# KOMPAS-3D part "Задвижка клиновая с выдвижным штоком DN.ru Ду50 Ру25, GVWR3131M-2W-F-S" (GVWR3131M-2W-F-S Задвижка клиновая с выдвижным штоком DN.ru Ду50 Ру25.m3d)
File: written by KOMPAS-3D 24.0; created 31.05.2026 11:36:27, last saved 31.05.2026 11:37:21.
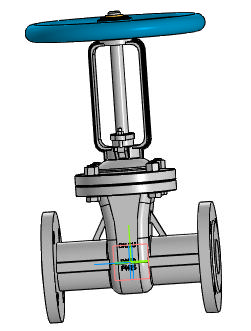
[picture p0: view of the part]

Document properties: Автор: R2D2; Полное имя файла: E:\Работа\Зайцев\GVWR3131M-2W-F-S Задвижка клиновая 30нж64нж DN.ru  Ду50-150 Ру25\исходные данные\DN50\GVWR3131M-2W-F-S Задвижка клиновая с выдвижным штоком DN.ru Ду50 Ру25.m3d

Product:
- Component [detail]: Деталь2  | qty 1  | pos. 1  | Масса: 3.95529; Автор: R2D2; additional columns: Типовые; source file: Деталь2 Деталь2.m3d
- Component [detail]: AS 1110 - M12 x 45  | qty 4  | pos. 2  | Комментарий: Болты и винты   шестигранные точные   метрические ISO; Автор: R2D2; additional columns: Сталь, мягкая; source file: AS 1110 - M12 x 45 AS 1110 - M12 x 45.m3d
- Component [detail]: ANSI B18.2.4.2M - M12x1,75 - 18  | designation ANSI B18.2.4.2M - M12x1,75  | qty 4  | pos. 3  | Комментарий: Типы метрических   шестигранных гаек   2; Автор: R2D2; additional columns: Сталь, мягкая; source file: ANSI B18.2.4.2M - M12x1,75 ANSI B18.2.4.2M - M12x1,75 - 18.m3d
- Component [detail]: ANSI B18.2.4.2M - M5x0,8 - 8  | designation ANSI B18.2.4.2M - M5x0,8  | qty 1  | pos. 4  | Комментарий: Типы метрических   шестигранных гаек   2; Автор: R2D2; additional columns: Сталь, мягкая; source file: ANSI B18.2.4.2M - M5x0,8 ANSI B18.2.4.2M - M5x0,8 - 8.m3d
- Component [detail]: Деталь1  | qty 1  | pos. 5  | Автор: R2D2; additional columns: Типовые; source file: 2.m3d
- Component [detail]: Деталь1  | qty 1  | pos. 5  | Автор: R2D2; additional columns: Типовые; source file: 1.m3d
- Component [detail]: Деталь1  | designation Деталь1-01  | qty 1  | pos. 6  | Автор: R2D2; additional columns: Типовые; source file: 1.m3d
- Component [detail]: ANSI B18.2.4.2M - M5x0,8 - 8  | designation ANSI B18.2.4.2M - M5x0,8-01  | qty 1  | pos. 7  | Комментарий: Типы метрических   шестигранных гаек   2; Автор: R2D2; additional columns: Сталь, мягкая; source file: ANSI B18.2.4.2M - M5x0,8 ANSI B18.2.4.2M - M5x0,8 - 8.m3d
- Component [detail]: Деталь1  | qty 1  | Автор: R2D2; additional columns: Типовые; source file: 3.m3d
- Part/product: Задвижка клиновая с выдвижным штоком DN.ru Ду50 Ру25  | designation GVWR3131M-2W-F-S
    Масса: 14
    Раздел спецификации: Прочие изделия
    Примечание: D040-08600

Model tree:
1. Массив по концентрической сетке:1  (labels: Грань.Твердое тело1)  (4 pattern instances)
     Шаг 2 = 360
2. Эскиз:1
3. Элемент выдавливания:1  (labels: Грань.Твердое тело1)
     Расстояние 1 = 46; Смещение 1 = 1
4. Элемент выдавливания:2  (with: Грань.Элемент выдавливания:1, Грань.Элемент вращения:1)
     Расстояние 1 = 42.9933
5. Элемент выдавливания:3  (with: Грань.Элемент выдавливания:1, Грань.Элемент вращения:1)
     Расстояние 1 = 44.6136
6. Элемент выдавливания:4  (with: Грань.Элемент выдавливания:1, Грань.Элемент вращения:1)  (labels: Грань.Твердое тело1; Грань.Solid1; Solid1; Твердое тело1)
     Расстояние 1 = 54.75; Расстояние = -125; Ориентация = 2; Ориентация = 2; Расстояние = -362.5

Referenced files in E:\Работа\Зайцев\GVWR3131M-2W-F-S Задвижка клиновая 30нж64нж DN.ru  Ду50-150 Ру25\исходные данные\DN50\: Деталь2 Деталь2.m3d, AS 1110 - M12 x 45 AS 1110 - M12 x 45.m3d, ANSI B18.2.4.2M - M12x1,75 ANSI B18.2.4.2M - M12x1,75 - 18.m3d, ANSI B18.2.4.2M - M5x0,8 ANSI B18.2.4.2M - M5x0,8 - 8.m3d, 2.m3d, 1.m3d, 3.m3d
Referenced files in E:\Работа\Зайцев\GVWR3131M-2W-F-S Задвижка клиновая с выдвижным штоком DN.ru Ду50-200 Ру63\DN50\исходные материалы\: ANSI B18.2.4.2M - M12x1,75 ANSI B18.2.4.2M - M12x1,75 - 18.m3d, AS 1110 - M12 x 45 AS 1110 - M12 x 45.m3d
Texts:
  GVWR3131M-2W-F-S
  DN50
  GOST 26.020 Pr3
  PN25
  Деталь2 Деталь2
  AS 1110 - M12 x 45 AS 1110 - M12 x 45 (1)
  ANSI B18.2.4.2M - M12x1,75 ANSI B18.2.4.2M - M12x1,75 - 18 (1)
  ANSI B18.2.4.2M - M5x0,8 ANSI B18.2.4.2M - M5x0,8 - 8
  Деталь1 Деталь1
  Деталь1-01 Деталь1
  ANSI B18.2.4.2M - M5x0,8-01 ANSI B18.2.4.2M - M5x0,8 - 8
  Ось Y.Начало координат
  Ось Z.Начало координат
  Плоскость ZX.Начало координат
  Плоскость XY.Начало координат
  Плоскость ZY.Начало координат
